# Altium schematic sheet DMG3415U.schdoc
size 127 x 101 mm
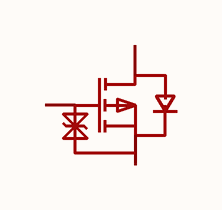
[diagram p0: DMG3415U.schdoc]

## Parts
Q?  dmg3415u  [SOT-23-3_L2.9-W1.3-P1.90-LS2.4-BR-1]  (value not drawn)

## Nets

Not connected (* = marked no-connect by the designer): Q? 1(G) 2(S) 3(D)

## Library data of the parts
Q? = dmg3415u: 漏源电压(Vdss):20V;连续漏极电流(Id):4A;导通电阻(RDS(on)):49mΩ@2.5V,4A;耗散功率(Pd):1.4W;阈值电压(Vgs(th)):350mV;; Manufacturer: TECH PUBLIC(台舟); AddInBom: yes; ModelId: c62791f0466c4ae2a892c056b845b0ca; ModelName: SOT-23-3P_L2.9-W1.3-H1.0-LS2.4-P0.95; ModelTransform: 98.425,114.173,0,180,0,0,0.0005,-0.0005,0; Drain to Source Voltage: 20V; Pd - Power Dissipation: 1.4W; Gate Threshold Voltage (Vgs(th)@Id): 350mV; Input Capacitance(Ciss@Vds): 1.1811nF@10V; Reverse Transfer Capacitance (Crss@Vds): 114.8pF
